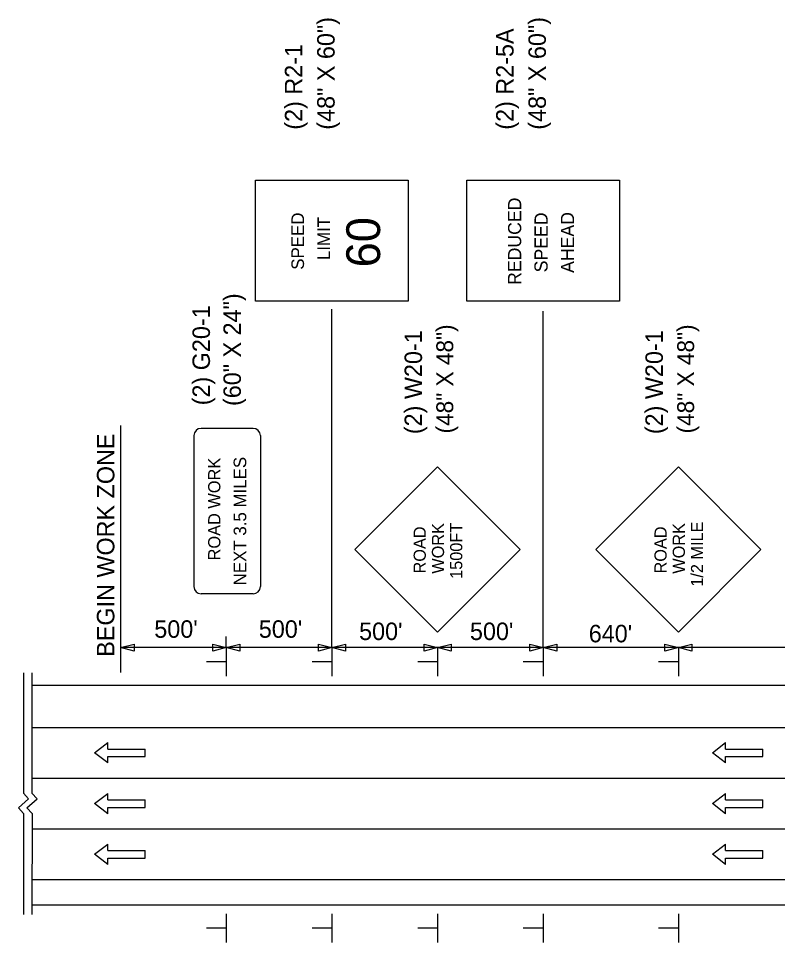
# Model space of a CAD drawing. Extents: x 1017892 to 1236694, y 658553 to 792468.
# Drawn here: x 1023203 to 1023877, y 659722 to 660542 of the extents above; entities that cross this region are included whole.
import ezdxf

# ---------------------------------------------------------------- set-up
doc = ezdxf.new("R2010")
doc.units = 0
for name, color, linetype in [('Level 1', 7, 'Continuous'), ('Level 3', 7, 'Continuous'), ('Level 42', 7, 'Continuous'), ('Level 8', 7, 'Continuous'), ('R_Const Phase All', 7, 'Continuous'), ('R_Proposed Road Annot', 7, 'Continuous')]:
    doc.layers.add(name, color=color, linetype=linetype)

msp = doc.modelspace()

# ---------------------------------------------------------------- linework, layer by layer
at = {"layer": 'Level 1'}
for p, q in [((1023270.41, 659890.09), (1023282.09, 659899.09)), ((1023282.09, 659893.46), (1023282.09, 659899.09)), ((1023282.09, 659893.46), (1023315.19, 659893.46)), ((1023315.19, 659886.71), (1023315.19, 659893.46)), ((1023818.74, 659890.09), (1023830.43, 659899.09)), ((1023830.43, 659893.46), (1023830.43, 659899.09)), ((1023830.43, 659893.46), (1023863.53, 659893.46)), ((1023863.53, 659886.71), (1023863.53, 659893.46)), ((1023282.09, 659881.09), (1023270.41, 659890.09)), ((1023282.09, 659886.71), (1023315.19, 659886.71)), ((1023282.09, 659881.09), (1023282.09, 659886.71)), ((1023830.43, 659881.09), (1023818.74, 659890.09)), ((1023830.43, 659886.71), (1023863.53, 659886.71)), ((1023830.43, 659881.09), (1023830.43, 659886.71)), ((1023270.41, 659845.09), (1023282.09, 659854.09)), ((1023282.09, 659848.46), (1023282.09, 659854.09)), ((1023818.74, 659845.09), (1023830.43, 659854.09)), ((1023830.43, 659848.46), (1023830.43, 659854.09)), ((1023282.09, 659836.09), (1023270.41, 659845.09)), ((1023282.09, 659848.46), (1023315.19, 659848.46)), ((1023315.19, 659841.71), (1023315.19, 659848.46)), ((1023830.43, 659836.09), (1023818.74, 659845.09)), ((1023830.43, 659848.46), (1023863.53, 659848.46)), ((1023863.53, 659841.71), (1023863.53, 659848.46)), ((1023282.09, 659841.71), (1023315.19, 659841.71)), ((1023282.09, 659836.09), (1023282.09, 659841.71)), ((1023830.43, 659841.71), (1023863.53, 659841.71)), ((1023830.43, 659836.09), (1023830.43, 659841.71)), ((1023270.41, 659800.09), (1023282.09, 659809.09)), ((1023282.09, 659803.46), (1023282.09, 659809.09)), ((1023282.09, 659803.46), (1023315.19, 659803.46)), ((1023315.19, 659796.71), (1023315.19, 659803.46)), ((1023818.74, 659800.09), (1023830.43, 659809.09)), ((1023830.43, 659803.46), (1023830.43, 659809.09)), ((1023830.43, 659803.46), (1023863.53, 659803.46)), ((1023863.53, 659796.71), (1023863.53, 659803.46)), ((1023282.09, 659791.09), (1023270.41, 659800.09)), ((1023282.09, 659796.71), (1023315.19, 659796.71)), ((1023282.09, 659791.09), (1023282.09, 659796.71)), ((1023830.43, 659791.09), (1023818.74, 659800.09)), ((1023830.43, 659796.71), (1023863.53, 659796.71)), ((1023830.43, 659791.09), (1023830.43, 659796.71))]:
    msp.add_line(p, q, dxfattribs=at)
at = {"layer": 'Level 3'}
for p, q in [((1023387.32, 659983.39), (1023387.32, 659958.08)), ((1023481.07, 659983.39), (1023481.07, 659958.08)), ((1023574.82, 659983.39), (1023574.82, 659958.08)), ((1023668.57, 659983.39), (1023668.57, 659958.08)), ((1023788.57, 659983.39), (1023788.57, 659958.08)), ((1023386.95, 659970.8), (1023369.68, 659970.8)), ((1023480.7, 659970.8), (1023463.43, 659970.8)), ((1023574.45, 659970.8), (1023557.18, 659970.8)), ((1023668.2, 659970.8), (1023650.93, 659970.8)), ((1023788.2, 659970.8), (1023770.93, 659970.8)), ((1023387.32, 659747.08), (1023387.32, 659721.77)), ((1023481.07, 659747.08), (1023481.07, 659721.77)), ((1023574.82, 659747.08), (1023574.82, 659721.77)), ((1023668.57, 659747.08), (1023668.57, 659721.77)), ((1023788.57, 659747.08), (1023788.57, 659721.77)), ((1023386.95, 659734.49), (1023369.68, 659734.49)), ((1023480.7, 659734.49), (1023463.43, 659734.49)), ((1023574.45, 659734.49), (1023557.18, 659734.49)), ((1023668.2, 659734.49), (1023650.93, 659734.49)), ((1023788.2, 659734.49), (1023770.93, 659734.49))]:
    msp.add_line(p, q, dxfattribs=at)
for centre, start, end in [((1023365.02, 660171.51), 90, 180), ((1023411.13, 660171.51), 0, 90), ((1023365.02, 660037.55), 180, 270), ((1023411.13, 660037.55), 270, 0)]:
    msp.add_arc(centre, 6.46, start, end, dxfattribs=at)
at = {"layer": 'Level 42'}
for p, q in [((1023358.56, 660171.51), (1023358.56, 660037.55)), ((1023411.13, 660177.96), (1023365.02, 660177.96)), ((1023417.59, 660171.51), (1023417.59, 660037.55)), ((1023411.13, 660031.09), (1023365.02, 660031.09))]:
    msp.add_line(p, q, dxfattribs=at)
at = {"layer": 'Level 8'}
for p, q in [((1023574.82, 660143.69), (1023501.52, 660070.38)), ((1023574.82, 660143.69), (1023648.06, 660070.39)), ((1023788.57, 660143.69), (1023715.27, 660070.38)), ((1023788.57, 660143.69), (1023861.81, 660070.39)), ((1023501.52, 660070.38), (1023574.82, 659997.09)), ((1023648.06, 660070.39), (1023574.82, 659997.09)), ((1023715.27, 660070.38), (1023788.57, 659997.09)), ((1023861.81, 660070.39), (1023788.57, 659997.09))]:
    msp.add_line(p, q, dxfattribs=at)
for points in [[(1023413.35, 660398.21), (1023548.8, 660398.21), (1023548.8, 660290.74), (1023413.35, 660290.74)], [(1023600.85, 660398.21), (1023736.3, 660398.21), (1023736.3, 660290.74), (1023600.85, 660290.74)]]:
    msp.add_lwpolyline(points, close=True, dxfattribs=at)
at = {"layer": 'R_Const Phase All'}
for p, q in [((1023207.37, 659961.16), (1023207.37, 659854.35)), ((1023214.87, 659961.16), (1023214.87, 659854.35)), ((1023214.87, 659950.09), (1024375.31, 659950.09)), ((1023214.87, 659912.59), (1024375.31, 659912.59)), ((1023214.87, 659867.59), (1024375.31, 659867.59)), ((1023207.37, 659854.35), (1023211.88, 659849.13)), ((1023214.87, 659854.35), (1023219.38, 659849.13)), ((1023202.89, 659841.37), (1023211.88, 659849.13)), ((1023210.39, 659841.37), (1023219.38, 659849.13)), ((1023202.89, 659841.37), (1023207.4, 659836.15)), ((1023207.4, 659836.15), (1023207.36, 659746.49)), ((1023210.39, 659841.37), (1023214.9, 659836.15)), ((1023214.9, 659836.15), (1023214.86, 659746.49)), ((1023214.87, 659822.59), (1024375.31, 659822.59)), ((1023214.87, 659777.59), (1024375.31, 659777.59)), ((1023214.87, 659755.09), (1024375.31, 659755.09))]:
    msp.add_line(p, q, dxfattribs=at)
at = {"layer": 'R_Proposed Road Annot'}
for p, q in [((1023481.07, 659983.39), (1023481.07, 660283.73)), ((1023668.57, 659983.39), (1023668.57, 660281.96)), ((1023293.57, 660180.55), (1023293.57, 659961.32)), ((1023387.32, 659983.39), (1023387.32, 659993.39))]:
    msp.add_line(p, q, dxfattribs=at)
for points in [[(1023305.57, 659980.39), (1023293.57, 659983.39), (1023305.57, 659986.39)], [(1023375.32, 659986.39), (1023387.32, 659983.39), (1023375.32, 659980.39)], [(1023399.32, 659980.39), (1023387.32, 659983.39), (1023399.32, 659986.39)], [(1023469.07, 659986.39), (1023481.07, 659983.39), (1023469.07, 659980.39)], [(1023493.07, 659980.39), (1023481.07, 659983.39), (1023493.07, 659986.39)], [(1023562.82, 659986.39), (1023574.82, 659983.39), (1023562.82, 659980.39)], [(1023586.82, 659980.39), (1023574.82, 659983.39), (1023586.82, 659986.39)], [(1023656.57, 659986.39), (1023668.57, 659983.39), (1023656.57, 659980.39)], [(1023680.57, 659980.39), (1023668.57, 659983.39), (1023680.57, 659986.39)], [(1023776.57, 659986.39), (1023788.57, 659983.39), (1023776.57, 659980.39)], [(1023800.57, 659980.39), (1023788.57, 659983.39), (1023800.57, 659986.39)]]:
    msp.add_lwpolyline(points, close=True, dxfattribs=at)
for points in [[(1023387.32, 659983.39), (1023293.57, 659983.39)], [(1023481.07, 659983.39), (1023387.32, 659983.39)], [(1023574.82, 659983.39), (1023481.07, 659983.39)], [(1023668.57, 659983.39), (1023574.82, 659983.39)], [(1023788.57, 659983.39), (1023668.57, 659983.39)], [(1024036.07, 659983.39), (1023788.57, 659983.39)]]:
    msp.add_lwpolyline(points, dxfattribs=at)

# ---------------------------------------------------------------- texts
at = {"layer": 'Level 3'}
msp.add_text('NEXT 3.5 MILES', height=11.1942, rotation=90, dxfattribs=at).set_placement((1023405.03, 660038.68))
at = {"layer": 'Level 42'}
msp.add_text('ROAD WORK', height=10.847, rotation=90, dxfattribs=at).set_placement((1023382.06, 660060.8))
at = {"layer": 'Level 8'}
for s, height, rotation, p in [('(48" X 60")', 15.5, 90, (1023483.48, 660442.94)), ('(48" X 60")', 15.5, 90, (1023670.98, 660442.94)), ('(2) R2-5A', 15.5, 90, (1023642.31, 660442.94)), ('(2) R2-1', 15.5, 90, (1023454.81, 660442.94)), ('REDUCED', 11.719, 90, (1023649.08, 660305.23)), ('SPEED', 11.194, 90, (1023456.31, 660318.7)), ('SPEED', 11.719, 90, (1023672.52, 660316.39)), ('AHEAD', 11.717, 90, (1023695.95, 660315.88)), ('LIMIT', 11.194, 90, (1023479.44, 660327.28)), ('60', 30, 90, (1023523.84, 660320.78)), ('(60" X 24")', 15.5, 90, (1023400.3, 660197.78)), ('(2) G20-1', 15.5, 90, (1023372.83, 660198.4)), ('(2) W20-1', 15.5, 90, (1023561.05, 660172.82)), ('(48" X 48")', 15, 90, (1023588.74, 660173.44)), ('(2) W20-1', 15.5, 90, (1023774.8, 660172.82)), ('(48" X 48")', 15, 90, (1023802.49, 660173.44)), ('ROAD', 10.799, 90.00045, (1023564.38, 660049.21)), ('WORK', 10.797, 90.00004, (1023580.58, 660049)), ('1500FT', 10.799, 90.00057, (1023596.78, 660044.41)), ('ROAD', 10.799, 90.00045, (1023778.13, 660049.21)), ('WORK', 10.797, 90.00004, (1023794.33, 660049)), ('1/2 MILE', 10.799, 90.00057, (1023810.53, 660037.48))]:
    msp.add_text(s, height=height, rotation=rotation, dxfattribs=at).set_placement(p)
at = {"layer": 'R_Proposed Road Annot'}
msp.add_text('BEGIN WORK ZONE', height=15.5, rotation=90, dxfattribs=at).set_placement((1023288, 659975.31))
for s, p in [("500'", (1023323.43, 659992.15)), ("500'", (1023416.2, 659992.15)), ("500'", (1023505.2, 659990.14)), ("500'", (1023603.57, 659990.14)), ("640'", (1023709.01, 659988.11))]:
    msp.add_text(s, height=15.5, dxfattribs=at).set_placement(p)

doc.saveas('drawing.dxf')
